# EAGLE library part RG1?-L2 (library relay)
HIGH FREQUENCY RELAYS WITH 1C AND 2C CONTACTS NAiS Source: http://www.mew-europe.com/.. en_ds_61302_0000.pdf
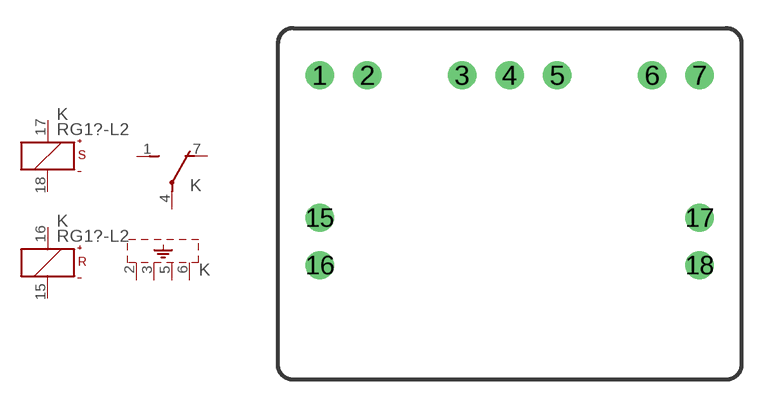
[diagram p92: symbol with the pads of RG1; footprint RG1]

Designator prefix K; gates 1=U S1=SHIELD-4 R=K+-R S=K+-S

## RG1-L2 (OC_FARNELL: unknown; OC_NEWARK: unknown)  [RG1]
1  1:S  pas
2  S1:SH  pas
3  S1:SH  pas
4  1:P  pas
5  S1:SH  pas
6  S1:SH  pas
7  1:O  pas
15  R:-  pas
16  R:+  pas
17  S:+  pas
18  S:-  pas

## Footprint RG1 (pad centres in mm)
HIGH FREQUENCY RELAYS WITH 1C AND 2C CONTACTS NAiS Source: http://www.mew-europe.com/.. en_ds_61302_0000.pdf
drill 1 round: 1 -10.16,7.62; 2 -7.62,7.62; 3 -2.54,7.62; 4 0,7.62; 5 2.54,7.62; 6 7.62,7.62; 7 10.16,7.62; 15 -10.16,0; 16 -10.16,-2.54; 17 10.16,0; 18 10.16,-2.54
